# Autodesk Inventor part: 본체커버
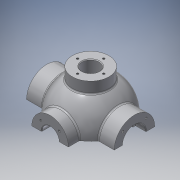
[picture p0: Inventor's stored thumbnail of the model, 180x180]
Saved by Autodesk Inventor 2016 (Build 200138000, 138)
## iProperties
Created: 2015-12
Part Number: 본체커버
Material: 알루미늄 6061
Document SubType Name: Modeling
Designer: mduedu
Density: 2.71 g/cm^3
Mass: 574.083 g
Surface Area: 451.737 cm^2
Volume: 211.839 cm^3
Appearance: 알루미늄 - 평지
Author: mduedu
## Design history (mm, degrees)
sketch "스케치1"
  geometry: L1 (-53, 0)-(53, 0); A1 r 53 centre (0, 0) between (53, 0) and (-53, 0); 2 further points
  constraints: 2 coincident, 2 end point, 2 point on circle, 1 centre point, 1 horizontal, 1 midpoint
  dimensions: "d0" = 53 radius of A1
revolve "회전1" sketch "스케치1" stored, may be unused: angle "d2" = 90 deg
feature "쉘1" dims "d11" = 10
node "작업 평면1"
sketch "스케치2"
  geometry: C1 r 31 at (0, 0); 1 further point
  constraints: 1 centre point, 1 coincident
  dimensions: "d4" = 62 diameter of C1
extrude "돌출1" join sketch "스케치2" stored distance "d5" = 10; taper "d6" = 0 deg
node "작업 평면2"
sketch "스케치3"
  geometry: C1 r 28 at (0, 0); 1 further point
  constraints: 1 centre point, 1 coincident
  dimensions: "d8" = 56 diameter of C1
extrude "돌출2" join sketch "스케치3" stored distance "d9" = 10; taper "d10" = 0 deg
hole "구멍1" diameter "d14" = 35; stored, may be unused: countersink angle "d18" = 90 deg, drill point angle "d20" = 0 deg; dims "d12" = 10, "d13" = 10, "d15" = 6, "d16" = 4, "d17" = 2, "d19" = 16
hole "구멍2" diameter "d23" = 27; stored, may be unused: countersink angle "d27" = 90 deg, drill point angle "d29" = 0 deg; dims "d21" = 10, "d22" = 10, "d24" = 6, "d25" = 4, "d26" = 2, "d28" = 16
fillet "모깎기1" dims "d30" = 0.3
hole "구멍3" diameter "d33" = 26; stored, may be unused: countersink angle "d37" = 90 deg, drill point angle "d39" = 0 deg; dims "d31" = 10, "d32" = 10, "d34" = 6, "d35" = 4, "d36" = 2, "d38" = 16
chamfer "모따기1" distance "d40" = 1; stored, may be unused: second distance "d41" = 2, angle "d42" = 45 deg
sketch "스케치4"
  geometry: L1 (0, 0)-(0, -25); L2 (0, 0)-(-17.678, -17.678); A1 r 25 centre (0, 0) between (-17.678, -17.678) and (0, -25); 1 further point
  constraints: 4 end point, 2 point on circle, 1 centre point, 1 coincident, 1 vertical
  dimensions: "d43" = 50 diameter of A1; "d47" = 45 deg angle of L1 L2
hole "구멍4" sketch "스케치4" at (-17.678, -17.678) diameter "d49" = 3.242; stored, may be unused: countersink angle "d53" = 90 deg, drill point angle "d55" = 118 deg; dims "d50" = 11, "d51" = 4, "d52" = 2, "d54" = 13
sketch "스케치5"
  geometry: L1 (0, 0)-(0, -20); L2 (0, 0)-(-14.142, -14.142); A1 r 20 centre (0, 0) between (0, -20) and (-14.142, -14.142); 2 further points
  constraints: 4 end point, 2 coincident, 2 point on circle, 1 centre point, 1 vertical
  dimensions: "d59" = 40 diameter of A1; "d65" = 45 deg angle of L1 L2
hole "구멍5" sketch "스케치5" at (-14.142, -14.142) diameter "d67" = 3.242; stored, may be unused: countersink angle "d71" = 90 deg, drill point angle "d73" = 118 deg; dims "d68" = 8, "d69" = 4, "d70" = 2, "d72" = 10
node "작업 평면3"
sketch "스케치6"
  geometry: C1 r 65 at (0, 0); 1 further point
  constraints: 1 centre point, 1 coincident
  dimensions: "d78" = 130 diameter of C1
extrude "돌출3" join sketch "스케치6" distance "d80" = 10; taper "d81" = 0 deg
sketch "스케치7"
  geometry: C1 r 20 at (0, 0); 1 further point
  constraints: 1 centre point, 1 coincident
  dimensions: "d82" = 40 diameter of C1
extrude "돌출4" join sketch "스케치7" stored distance "d84" = 10; taper "d85" = 0 deg
sketch "스케치8"
  geometry: 2 further points
  constraints: 1 coincident
hole "구멍6" sketch "스케치8" at (0, 0) diameter "d86" = 20; stored, may be unused: countersink angle "d90" = 90 deg, drill point angle "d92" = 118 deg; dims "d87" = 7, "d88" = 40, "d89" = 5, "d91" = 10
fillet "모깎기2" dims "d93" = 0.3
sketch "스케치9"
  geometry: L1 (65, -75)-(-65, -75) reference; L2 (-45, -75)-(-38.245, -36.692); A1 r 53 centre (0, 0) between (42.988, 31) and (42.988, -31) reference; 1 further point
  constraints: 2 end point, 1 point on circle, 1 point on line
  dimensions: "d94" = 45 horizontal distance of L2.start point (0, 0); "d95" = 80 deg angle of L2 L1
feature "리브1" sketch "스케치9" dims "d96" = 1, "d97" = 8, "d98" = 0, "d99" = 0, "d100" = 1, "d101" = 1
sketch "스케치10"
  geometry: L1 (0, 0)-(0, -55); L2 (0, 0)-(-38.891, -38.891); A1 r 55 centre (0, 0) between (0, -55) and (-38.891, -38.891); 2 further points
  constraints: 4 end point, 2 coincident, 2 point on circle, 1 centre point, 1 vertical
  dimensions: "d105" = 110 diameter of A1; "d107" = 45 deg angle of L1 L2
hole "구멍7" sketch "스케치10" at (-38.891, -38.891) diameter "d109" = 10; stored, may be unused: countersink angle "d113" = 90 deg, drill point angle "d115" = 118 deg; dims "d110" = 7, "d111" = 40, "d112" = 5, "d114" = 10
fillet "모깎기3" dims "d120" = 3
fillet "모깎기4" dims "d121" = 3, "d122" = 3
fillet "모깎기5" dims "d123" = 3
fillet "모깎기6" dims "d124" = 3
sketch "스케치11"
  geometry: C1 r 5 at (-38.891, 38.891) reference; C2 r 5 at (38.891, 38.891) reference; C3 r 5 at (38.891, -38.891) reference; C4 r 5 at (-38.891, -38.891) reference; C5 r 20 at (0, 0) reference; C6 r 65 at (0, 0) reference; 1 further point
  constraints: 3 other
feature "엠보싱1" sketch "스케치11" dims "d125" = 0.5, "d126" = 0
sketch "스케치12"
  geometry: L1 (0, 100)-(0, -100); L2 (0, 100)-(-150, 100); L3 (-150, 100)-(-150, -100); L4 (-150, -100)-(0, -100); 2 further points
  constraints: 8 end point, 3 perpendicular, 1 coincident, 1 midpoint, 1 vertical
  dimensions: "d127" = 200 distance of L2.end L3.end; "d129" = 150 distance of L3.end L1.end
extrude "돌출5" cut sketch "스케치12" stored distance "d130" = 10; taper "d131" = 0 deg
sketch "스케치13"
  geometry: C1 r 7 at (0, -53); A1 r 53 centre (0, 0) between (-42.113, -32.179) and (42.113, -32.179) reference; 1 further point
  constraints: 1 centre point, 1 point on circle
  dimensions: "d132" = 14 diameter of C1
extrude "돌출6" join sketch "스케치13" distance "d133" = 5; taper "d134" = 0 deg
sketch "스케치14"
  geometry: C1 r 7 at (0, 0) reference; 1 further point
extrude "돌출7" cut sketch "스케치14" stored distance "d135" = 5; taper "d136" = 0 deg
sketch "스케치15"
  geometry: C1 r 2.25 at (0, 53); A1 r 7 centre (0, 53) between (6.965, 52.302) and (-6.965, 52.302) reference; 1 further point
  constraints: 1 centre point, 1 coincident
  dimensions: "d139" = 4.5 diameter of C1
extrude "돌출8" cut sketch "스케치15" stored distance "d141" = 5; taper "d142" = 0 deg
fillet "모깎기7" dims "d143" = 3
fillet "모깎기8" dims "d144" = 1
fillet "모깎기9" dims "d145" = 1
fillet "모깎기10" dims "d146" = 1
node "작업 평면4"
sketch "스케치16"
  geometry: C1 r 28 at (0, 0); 1 further point
  constraints: 1 centre point, 1 coincident
  dimensions: "d148" = 56 diameter of C1
extrude "돌출9" join sketch "스케치16" stored distance "d150" = 5; taper "d151" = 0 deg
hole "구멍8" diameter "d154" = 26; stored, may be unused: countersink angle "d158" = 90 deg, drill point angle "d160" = 118 deg; dims "d152" = 10, "d153" = 10, "d155" = 6, "d156" = 4, "d157" = 2, "d159" = 8
sketch "스케치17" dims "d161" = 40
  geometry: 3 further points
  constraints: 2 vertical alignment, 1 coincident, 2 other
hole "구멍9" sketch "스케치17" at (0, 20) diameter "d163" = 3.242; stored, may be unused: countersink angle "d167" = 90 deg, drill point angle "d169" = 118 deg; dims "d164" = 8, "d165" = 4, "d166" = 2, "d168" = 10
fillet "모깎기11" dims "d173" = 3
chamfer "모따기2" distance "d174" = 1; stored, may be unused: second distance "d175" = 2, angle "d176" = 45 deg
node "솔리드1"
mirror "대칭1"
mirror "대칭2"
pattern_circular "원형 패턴1" dims angle "d57" = 360 deg
mirror "대칭3"
pattern_circular "원형 패턴2" dims angle "d75" = 360 deg
pattern_circular "원형 패턴3" dims angle "d103" = 360 deg
pattern_circular "원형 패턴4" dims angle "d118" = 360 deg
pattern_circular "원형 패턴5" dims angle "d171" = 360 deg
node "투영된 루프1"
other parameters: "d3" = 67, "d7" = 62, "d77" = -85, "d147" = 62
